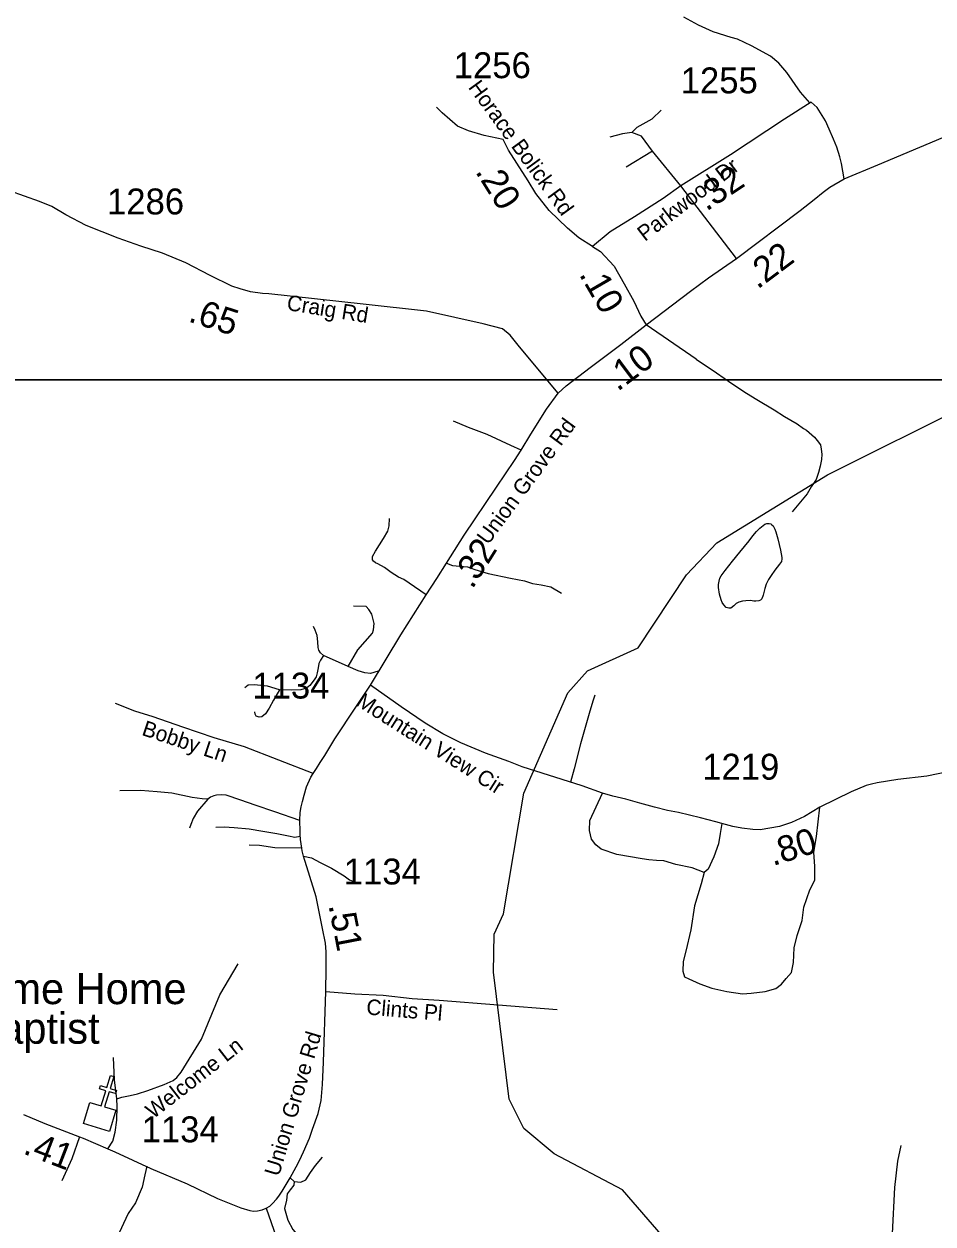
# Model space of a CAD drawing. Extents: x 1159738 to 1321356, y 736314 to 882035.
# Drawn here: x 1239757 to 1244144, y 762683 to 768473 of the extents above; entities that cross this region are included whole.
import ezdxf

# ---------------------------------------------------------------- set-up
doc = ezdxf.new("R2010")
doc.units = 0
for name, color, linetype in [('Exist Cultural Church CELL', 7, 'Continuous'), ('Exist Cultural Church Label', 7, 'Continuous'), ('Exist Hydrographic Creek Single Shore', 7, 'Continuous'), ('Exist Hydrographic Misc Water Feature', 7, 'Continuous'), ('Exist Road Non-System Type 51', 7, 'Continuous'), ('Exist Road Non-System Type 51 Label', 7, 'Continuous'), ('Exist Road Secondary Mileage Hundredths English Label', 7, 'Continuous'), ('Exist Road Secondary Type 51 Attributed', 7, 'Continuous'), ('Exist Road Secondary Type 51 Label', 7, 'Continuous'), ('Exist Road Secondary Type 51 Number Label', 7, 'Continuous'), ('Map Preparation Inset Cut Line', 7, 'Continuous')]:
    doc.layers.add(name, color=color, linetype=linetype)

msp = doc.modelspace()

# ---------------------------------------------------------------- linework, layer by layer
at = {"layer": 'Exist Cultural Church CELL'}
msp.add_lwpolyline([(1240075.5, 763270.1), (1240129.9, 763253.5), (1240152.3, 763326.2), (1240121.7, 763335.7), (1240126.4, 763350.9), (1240157, 763341.5), (1240174.7, 763399), (1240190, 763394.3), (1240172.3, 763336.8), (1240202.9, 763327.4), (1240198.2, 763312.1), (1240167.6, 763321.5), (1240145.2, 763248.8), (1240200.3, 763231.7), (1240169, 763129.9), (1240044.2, 763168.4)], close=True, dxfattribs=at)
at = {"layer": 'Exist Hydrographic Creek Single Shore'}
msp.add_lwpolyline([(1244180.5, 759964.7), (1244084.4, 760107.8), (1243958.4, 760753.7), (1243698.4, 761343.2), (1243441.4, 761719.2), (1243308.4, 762020.6), (1243058.4, 762370.3), (1242645.4, 762848), (1242316.4, 763022), (1242169.4, 763143.2), (1242098.4, 763285.7), (1242022.4, 763897.8), (1242026.4, 764081.5), (1242071.3, 764179.1), (1242169.3, 764761.4), (1242382.4, 765246.3), (1242476.4, 765352.7), (1242721.3, 765462.7), (1242955.3, 765815.8), (1243101.3, 765970.4), (1243635.3, 766297.8), (1244319.3, 766638.6)], dxfattribs=at)
at = {"layer": 'Exist Hydrographic Misc Water Feature'}
msp.add_lwpolyline([(1243141.1, 765836.6), (1243176.2, 765881.9), (1243211.4, 765924.7), (1243256.8, 765979.5), (1243275.5, 766003), (1243292.1, 766024.8), (1243308.5, 766040.1), (1243333, 766060.1), (1243343, 766063.2), (1243353.1, 766063), (1243361, 766061.2), (1243366.9, 766056.9), (1243372.7, 766051.1), (1243380.5, 766036.2), (1243386, 766022.1), (1243395.1, 765988.3), (1243407.7, 765933.9), (1243414.9, 765899.3), (1243414.6, 765891.9), (1243412.4, 765879.6), (1243404.1, 765867.5), (1243381.3, 765838.4), (1243362.6, 765812.5), (1243350.1, 765793), (1243339.6, 765771.1), (1243332.9, 765749.9), (1243324.2, 765718), (1243317.7, 765700.2), (1243311.5, 765693.7), (1243303.5, 765690.6), (1243289.3, 765688.4), (1243279.4, 765688.6), (1243263.5, 765691.4), (1243241.3, 765690.2), (1243225.3, 765688.1), (1243207.2, 765682.7), (1243195, 765677.1), (1243182.7, 765665.1), (1243168.4, 765653.9), (1243158.4, 765654.1), (1243146.5, 765658.4), (1243134.8, 765671), (1243127.1, 765682.6), (1243121.5, 765695), (1243114.1, 765721.5), (1243108.9, 765753.6), (1243109.3, 765769.2), (1243111.7, 765785.5), (1243116.2, 765799.4), (1243122.4, 765810.7), (1243141.1, 765836.6)], dxfattribs=at)
at = {"layer": 'Exist Road Non-System Type 51'}
for p, q in [((1242790.5, 767859.4), (1242663.1, 767782.3)), ((1242926.8, 767691.5), (1242790.5, 767859.4)), ((1243195.2, 767342.2), (1242926.8, 767691.5)), ((1243001.1, 766855.5), (1242760.5, 767021.5)), ((1241322, 765373.8), (1241202.8, 765426.9)), ((1241041.5, 762906.4), (1241061.6, 762887.7))]:
    msp.add_line(p, q, dxfattribs=at)
for points in [[(1243549.1, 768092.3), (1243505.1, 768144.7), (1243439, 768239.7), (1243400.5, 768283.8), (1243360.5, 768318.3), (1243268.6, 768367.3), (1243201.1, 768400.3), (1243170.8, 768407.2), (1243084.1, 768434.8), (1243012.5, 768467.8), (1242942.3, 768506.4)], [(1242690.3, 767949.9), (1242717.3, 767974.6), (1242789.3, 768015.1), (1242832, 768057.9)], [(1242690.3, 767949.9), (1242645.4, 767943.1), (1242584.6, 767927.4)], [(1242790.5, 767859.4), (1242737.5, 767931.9), (1242690.3, 767949.9)], [(1243001.1, 766855.5), (1243099.8, 766789.5), (1243172.8, 766738), (1243244, 766692.5), (1243293.4, 766661.5), (1243378.4, 766611.8), (1243427.8, 766578.8), (1243489.1, 766543.5), (1243518.7, 766520.9), (1243534.5, 766512.6), (1243571.9, 766479.8), (1243585.5, 766463.5), (1243601.1, 766443.2), (1243604.7, 766421.1), (1243608.2, 766397.1), (1243605.7, 766371.1), (1243599.1, 766339.2), (1243592.5, 766309.3), (1243579.8, 766275.6), (1243567.4, 766255.8), (1243557, 766240), (1243536.4, 766206.4), (1243505.6, 766167), (1243464.6, 766119.8)], [(1242156.1, 766417.5), (1242106.6, 766440), (1241991.9, 766491.7), (1241902, 766525.5), (1241830, 766557)], [(1241698, 765719.5), (1241616.4, 765775.5), (1241590.4, 765792.8), (1241564.3, 765804.7), (1241528.7, 765827.3), (1241497.2, 765851.2), (1241464.3, 765868.5), (1241453.4, 765873.8), (1241443.8, 765881.8), (1241439.7, 765888.4), (1241439.7, 765903.1), (1241453.4, 765929.6), (1241491.7, 765990.8), (1241513.6, 766025.3), (1241519.1, 766051.9), (1241521.9, 766086.5)], [(1241796, 765871.7), (1241825.3, 765860.5), (1241860.9, 765857.9), (1241897.9, 765853.9), (1241933.5, 765840.6), (1241997.9, 765822), (1242104.8, 765799.4), (1242173.3, 765786.1), (1242211.7, 765772.8), (1242252.8, 765767.5), (1242299.3, 765756.9), (1242351.4, 765726.3)], [(1241322, 765373.8), (1241368.6, 765453.5), (1241438.5, 765533.3), (1241443.9, 765549.2), (1241446.7, 765579.8), (1241435.7, 765625), (1241422, 765647.6), (1241408.3, 765662.2), (1241348, 765664.8)], [(1241202.8, 765426.9), (1241187.7, 765438.9), (1241180.9, 765452.2), (1241176.8, 765465.5), (1241175.4, 765492.1), (1241171.3, 765522.6), (1241161.7, 765547.9), (1241154.7, 765565.5)], [(1241202.8, 765426.9), (1241187.7, 765404.3), (1241180.9, 765387.1), (1241176.8, 765367.1), (1241172.7, 765343.2), (1241167.2, 765323.3), (1241157.6, 765308.7), (1241137.1, 765282.1), (1241120.6, 765268.8), (1241093.2, 765260.8), (1241049.4, 765259.5), (1240990.5, 765260.8)], [(1241467.2, 765349.9), (1241430.2, 765339.2), (1241401.5, 765341.9), (1241370, 765352.5), (1241322, 765373.8)], [(1240990.5, 765260.8), (1240931.6, 765278.1), (1240868.5, 765284.7), (1240838.4, 765283.4), (1240823.3, 765270.1)], [(1240990.5, 765260.8), (1240961.7, 765210.3), (1240941.1, 765171.8), (1240923.3, 765143.9), (1240905.5, 765130.6), (1240891.8, 765129.2), (1240878.1, 765133.2), (1240872.6, 765142.5), (1240871.3, 765154.5)], [(1242513, 765235.1), (1242502, 765206.2), (1242485.5, 765146.9), (1242442.8, 764999.5), (1242412.5, 764879.7), (1242394.6, 764814.9)], [(1241152.9, 764856.8), (1240820.6, 764985.7), (1240675.4, 765028.2), (1240523.3, 765080.1), (1240380.1, 765130.6), (1240292.4, 765157.1), (1240199.3, 765194.4)], [(1240643.9, 764733.2), (1240617.8, 764734.5), (1240568.5, 764741.2), (1240469.9, 764761.1), (1240400, 764769.1), (1240319.2, 764774.4), (1240219.2, 764773.1)], [(1241087.8, 764630), (1240968.5, 764672), (1240872.6, 764703.9), (1240804.1, 764727.9), (1240732.9, 764751.8), (1240709.6, 764753.1), (1240686.3, 764751.8), (1240672.6, 764749.1), (1240657.6, 764742.5), (1240643.9, 764733.2)], [(1243040.5, 764379.2), (1242981.3, 764401.9), (1242902.5, 764418), (1242845.2, 764435.9), (1242809.4, 764437.7), (1242773.5, 764439.5), (1242741.3, 764444.9), (1242618.5, 764466.4), (1242543.3, 764491.5), (1242516.4, 764513), (1242496.7, 764539.9), (1242485.9, 764581.1), (1242487.7, 764629.5), (1242548.6, 764762.1)], [(1240643.9, 764733.2), (1240594.5, 764674.7), (1240574, 764640.2), (1240563, 764610.9), (1240556.2, 764592.3)], [(1243040.5, 764379.2), (1243026.2, 764323.7), (1242993.9, 764217.9), (1242976, 764103.2), (1242950.9, 763999.2), (1242938.4, 763949), (1242936.6, 763902.4), (1242945.6, 763875.6), (1242965.3, 763866.6), (1243019, 763841.5), (1243076.3, 763821.8), (1243149.7, 763805.7), (1243225, 763793.1), (1243266.2, 763796.7), (1243334.2, 763805.7), (1243386.2, 763820), (1243413, 763839.7), (1243436.3, 763868.4), (1243461.4, 763897.1), (1243470.4, 763945.5), (1243473.9, 764015.4), (1243488.3, 764074.5), (1243513.4, 764148), (1243520.5, 764212.5), (1243549.2, 764295), (1243574.3, 764341.6), (1243574.3, 764407.9), (1243568.9, 764477.8), (1243581.4, 764553.1), (1243597.5, 764694.1)], [(1241090.5, 764552.4), (1241064.4, 764548.4), (1241034.3, 764553.8), (1240976.8, 764565.7), (1240909.6, 764577.7), (1240843.9, 764588.3), (1240771.3, 764595), (1240723.3, 764597.6), (1240683.6, 764596.3)], [(1243124.7, 764614.9), (1243117.5, 764567.4), (1243108.5, 764517.3), (1243087.1, 764454.5), (1243058.4, 764395.4), (1243040.5, 764379.2)], [(1241098.1, 764496.6), (1240967.9, 764497.9), (1240893.9, 764508.6), (1240844.6, 764511.2)], [(1241105.8, 764458.2), (1241144.6, 764450.1), (1241187.1, 764427.5), (1241240.5, 764399.6), (1241302.1, 764363.7), (1241328.2, 764343.8), (1241367.9, 764327.8)], [(1240205.1, 763286.5), (1240229.8, 763295.8), (1240269.5, 763303.8), (1240305.1, 763310.5), (1240354.4, 763327.7), (1240433.8, 763356.5), (1240477.5, 763375.9), (1240494.7, 763389.8), (1240515.6, 763416.5), (1240613.1, 763575.3), (1240664, 763696.3), (1240703, 763788.6), (1240791, 763938.1)], [(1241214.5, 763805.5), (1241353.5, 763794.4), (1241490.7, 763787.6), (1241630.1, 763771.9), (1241760.5, 763762.8), (1242330.3, 763718.4)], [(1240205.1, 763286.5), (1240193.1, 763378.7), (1240188.3, 763485.8)], [(1240161.5, 763045.6), (1240185.9, 763083.2), (1240196.9, 763127), (1240205.1, 763184.2), (1240206.5, 763250.6), (1240205.1, 763286.5)], [(1240025.5, 763104.2), (1239987.6, 762997.4), (1239939.1, 762891.3)], [(1244162.9, 762175.3), (1244125.8, 762213.9), (1244052.8, 762262.1), (1243996.4, 762306.2), (1243956.4, 762348.9), (1243942.7, 762382), (1243937.2, 762415), (1243960.8, 762858.9), (1243974.6, 762985.7), (1243991.1, 763061.4)], [(1240350.5, 762961.8), (1240339.9, 762921), (1240327.5, 762860.7), (1240295.6, 762784.5), (1240260.2, 762733.1), (1240205.3, 762616), (1240148.6, 762509.7), (1240116.7, 762463.6)], [(1241061.6, 762887.7), (1241092.9, 762884.7), (1241117.6, 762895.9), (1241140.1, 762931.9), (1241164.8, 762965.7), (1241198.6, 763006.2)], [(1241061.6, 762887.7), (1241059.4, 762869.7), (1241041.4, 762847.2), (1241027.9, 762829.2), (1241023.4, 762797.7), (1241014.4, 762757.2), (1241030.1, 762701), (1241054.9, 762655.9), (1241090.9, 762613.2)]]:
    msp.add_lwpolyline(points, dxfattribs=at)
at = {"layer": 'Exist Road Secondary Type 51 Attributed'}
for points in [[(1243714.9, 767725.6), (1243877.3, 767793.7), (1244517.4, 768062.5), (1244715.8, 768145.8), (1244834.9, 768197.4), (1244907.5, 768226), (1245006.1, 768254), (1245116.9, 768289.8), (1245249.6, 768323.1), (1245666.1, 768436.9)], [(1242501.4, 767399.6), (1242434.3, 767442.1), (1242380.8, 767487.3), (1242291.8, 767573.7), (1242228.1, 767654.7), (1242189.7, 767715.9), (1242136.3, 767800.9), (1242095.2, 767864.7), (1242070.5, 767915.2), (1241977.4, 767935.2), (1241902, 767957.8), (1241848.6, 767980.3), (1241775.3, 768044.1), (1241747.9, 768072.3)], [(1243714.9, 767725.6), (1243702.4, 767799.9), (1243695, 767832.1), (1243679.9, 767878.4), (1243664.7, 767916.7), (1243643.3, 767965.7), (1243625.5, 768005.6), (1243584.5, 768069.6), (1243555.6, 768096), (1243427.9, 768014.5), (1243167.3, 767842), (1242926.8, 767691.5), (1242841.3, 767631.9), (1242704.2, 767543.1), (1242586.3, 767470), (1242501.4, 767399.6)], [(1242760.5, 767021.5), (1242974.7, 767184.3), (1243061.1, 767248.1), (1243195.2, 767342.2), (1243503.8, 767573.8), (1243570.8, 767626.4), (1243613.6, 767661.6), (1243646.8, 767685.5), (1243714.9, 767725.6)], [(1242335.6, 766691.2), (1242149.3, 766915.8), (1242104.1, 766971.6), (1242067.1, 767002.2), (1241974, 767026.1), (1241699.3, 767087.2), (1241393.8, 767120.5), (1240939.2, 767171.9), (1240908.5, 767172.3), (1240849.6, 767180.6), (1240801.2, 767194.9), (1240760.1, 767208.2), (1240656.1, 767259.1), (1240538, 767320), (1240424.8, 767368), (1240321.5, 767401.3), (1240212.1, 767439.1), (1240056.6, 767501), (1239959.5, 767551.7), (1239892, 767593.3), (1239831.4, 767616.6), (1239687.6, 767668.9)], [(1242501.4, 767399.6), (1242539.8, 767375.6), (1242604.8, 767305.2), (1242654.2, 767220.1), (1242700.7, 767135.1), (1242733.6, 767063.3), (1242760.5, 767021.5)], [(1242335.6, 766691.2), (1242373.3, 766727.1), (1242490.4, 766816.1), (1242579.5, 766882.6), (1242638.4, 766926.4), (1242760.5, 767021.5)], [(1241428.9, 765283.3), (1241575.7, 765525.4), (1241698, 765719.5), (1241749.3, 765798.1), (1241796, 765871.7), (1241815, 765901.7), (1241881.6, 766007.5), (1242038.3, 766238.4), (1242124.9, 766366.8), (1242156.1, 766417.5), (1242202.7, 766494.5), (1242279.5, 766614.1), (1242335.6, 766691.2)], [(1240925.7, 762758.9), (1240942.9, 762768.9), (1240957.2, 762782.8), (1240975.7, 762802.8), (1240987.4, 762818), (1241003.1, 762842), (1241041.5, 762906.4), (1241061.7, 762941.6), (1241080.2, 762976.2), (1241096.6, 763010.1), (1241105.5, 763031.5), (1241134.9, 763096.9), (1241149.7, 763140.7), (1241177.5, 763216.8), (1241191.2, 763278.6), (1241198, 763356.3), (1241202.8, 763463.3), (1241214.5, 763805.5), (1241215.8, 763915.8), (1241215.8, 763995.6), (1241211.7, 764038.1), (1241198, 764108.5), (1241167, 764261.2), (1241105.8, 764458.2), (1241100.1, 764483.3), (1241098.1, 764496.6), (1241091.8, 764537.8), (1241090.5, 764563.1), (1241090.5, 764595), (1241088.8, 764613.9), (1241087.8, 764630), (1241090.5, 764668.1), (1241094.6, 764696), (1241101.4, 764721.2), (1241109.7, 764751.8), (1241120.6, 764791.7), (1241141.8, 764839.7), (1241152.9, 764856.8), (1241168.6, 764881.2), (1241186.9, 764909.8), (1241208.3, 764943.2), (1241228.8, 764975.1), (1241257.6, 765024.2), (1241358.3, 765177.1), (1241428.9, 765283.3)], [(1244318, 764886), (1244114.6, 764844.2), (1243974.8, 764827.5), (1243874.8, 764811.6), (1243847.4, 764804.9), (1243821.4, 764798.3), (1243750.1, 764769), (1243597.5, 764694.1), (1243524.8, 764649.4), (1243461.8, 764620.2), (1243402.9, 764601.6), (1243356.3, 764593.6), (1243309.7, 764585.6), (1243274.1, 764587), (1243222, 764593.6), (1243178.2, 764601.6), (1243124.7, 764614.9), (1243096, 764624.2), (1243022, 764642.8), (1242916.5, 764668), (1242863.4, 764678.7), (1242799.7, 764694), (1242729.8, 764713.9), (1242662, 764732.5), (1242599.2, 764747.8), (1242548.6, 764762.1), (1242450.7, 764797), (1242161.6, 764888.7), (1242097.3, 764915.2), (1241984.9, 764955.1), (1241865, 765004.3), (1241778.7, 765048.1), (1241693.8, 765100), (1241577.3, 765178.4), (1241428.9, 765283.3)], [(1239754.4, 763210.7), (1239857.7, 763168.6), (1240025.5, 763104.2), (1240042.1, 763097.8), (1240161.5, 763045.6), (1240195.5, 763030.7), (1240368.6, 762951.3), (1240544.1, 762876.7), (1240690.8, 762805.7), (1240763.4, 762776.8), (1240803.8, 762761.6), (1240846.3, 762748.9), (1240864.8, 762745.6), (1240884.6, 762746.9), (1240906.5, 762750.9), (1240925.7, 762758.9)], [(1240925.7, 762758.9), (1240974.7, 762621.4), (1240993.2, 762523.7), (1241010.3, 762441.9), (1241032.2, 762362.2), (1241053.5, 762290.4), (1241078.1, 762217.3), (1241100.7, 762158.8), (1241126.8, 762096.6), (1241150.6, 762036.6)]]:
    msp.add_lwpolyline(points, dxfattribs=at)
at = {"layer": 'Map Preparation Inset Cut Line'}
for points in [[(1213574.8, 811005.5), (1289258, 811005.5), (1289258, 782300.2), (1274049.2, 782296.9), (1274049.2, 766757), (1213574.8, 766757)], [(1232800.5, 766757), (1308483.8, 766757), (1308483.8, 738579.5), (1232800.5, 738579.5)]]:
    msp.add_lwpolyline(points, close=True, dxfattribs=at)

# ---------------------------------------------------------------- texts
at = {"layer": 'Exist Cultural Church Label'}
for s, p in [('Welcome Home', (1239114.8, 763743.9)), ('Baptist', (1239508.7, 763552.9))]:
    msp.add_text(s, height=150, dxfattribs=at).set_placement(p)
at = {"layer": 'Exist Road Non-System Type 51 Label'}
for s, rotation, p in [('Bobby Ln', 341.635, (1240321.4, 765043.3)), ('Clints Pl', 355.18761, (1241407.2, 763694.3)), ('Welcome Ln', 37.88582, (1240380.9, 763187.7))]:
    msp.add_text(s, height=75, rotation=rotation, dxfattribs=at).set_placement(p)
at = {"layer": 'Exist Road Secondary Mileage Hundredths English Label'}
for s, rotation, p in [('.20', 302.13536, (1241932.7, 767760.8)), ('.32', 33.50189, (1243050.7, 767566.9)), ('.22', 36.88386, (1243297.9, 767190.5)), ('.10', 300.10657, (1242434, 767265.3)), ('.65', 342.08146, (1240545.5, 767039.1)), ('.10', 36.73134, (1242622.3, 766697.5)), ('.32', 57.80034, (1241920.8, 765742.8)), ('.80', 17.52851, (1243371.7, 764409.6)), ('.51', 281.00631, (1241226.3, 764220.7)), ('.41', 339.00096, (1239748, 763024.1))]:
    msp.add_text(s, height=125, rotation=rotation, dxfattribs=at).set_placement(p)
at = {"layer": 'Exist Road Secondary Type 51 Label'}
for s, rotation, p in [('Horace Bolick Rd', 306.07965, (1241898.5, 768167.3)), ('Parkwood Dr', 37.33823, (1242753.5, 767421.4)), ('Craig Rd', 350.77362, (1241021.8, 767093.5)), ('Union Grove Rd', 53.61756, (1241997.1, 765956.5)), ('Mountain View Cir', 327.64119, (1241355.3, 765188.3)), ('Union Grove Rd', 73.31196, (1240987.3, 762909.1))]:
    msp.add_text(s, height=75, rotation=rotation, dxfattribs=at).set_placement(p)
at = {"layer": 'Exist Road Secondary Type 51 Number Label'}
for s, p in [('1256', (1241831.4, 768211.6)), ('1255', (1242926.7, 768138.4)), ('1286', (1240157.9, 767554.3)), ('1134', (1240859.4, 765218.4)), ('1219', (1243030.5, 764827)), ('1134', (1241300.6, 764321.3)), ('1134', (1241300.6, 764321.3)), ('1134', (1241300.6, 764321.3)), ('1134', (1241300.6, 764321.3)), ('1134', (1241300.6, 764321.3)), ('1134', (1241300.6, 764321.3)), ('1134', (1240324.9, 763077.3))]:
    msp.add_text(s, height=125, dxfattribs=at).set_placement(p)

doc.saveas('drawing.dxf')
